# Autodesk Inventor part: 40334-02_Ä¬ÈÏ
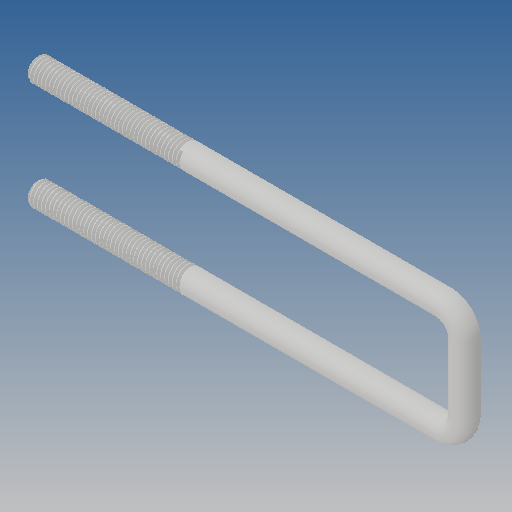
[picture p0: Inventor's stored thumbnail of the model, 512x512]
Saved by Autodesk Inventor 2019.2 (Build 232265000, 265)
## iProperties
Created: 2010-06
Part Number: 40334-02_Ä¬ÈÏ
Material: Ogólny
Document SubType Name: Modeling
Designer: CADENGINEERING4
Density: 1 g/cm^3
Appearance: Domyślna
Author: CADENGINEERING4
Revision Number: ÈÎºÎ
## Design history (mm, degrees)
feature "NONE"
node "Bryła1"
